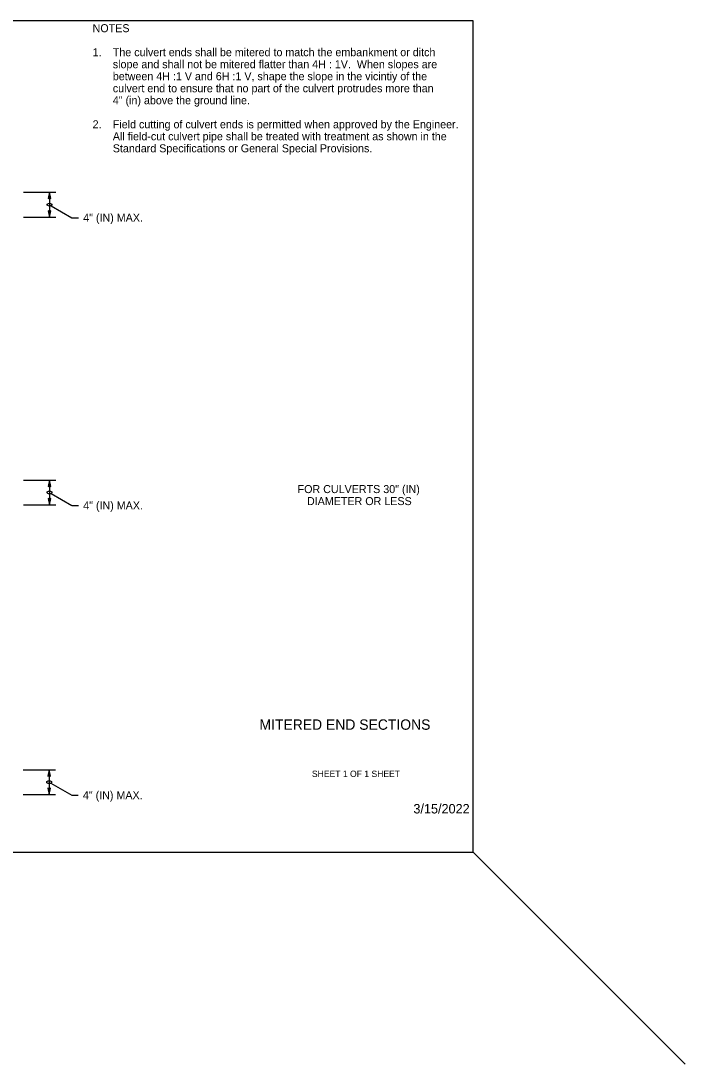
# Model space of a CAD drawing. Extents: x 99862 to 103680, y 99470 to 102076.
# Drawn here: x 102021 to 103680, y 99470 to 102076 of the extents above; entities that cross this region are included whole.
import ezdxf

# ---------------------------------------------------------------- set-up
doc = ezdxf.new("R2010")
doc.units = 0
for name, color, linetype in [('Default', 7, 'Continuous'), ('Level 1', 7, 'Continuous'), ('Level 15', 7, 'Continuous'), ('Level 20', 7, 'Continuous'), ('Level 60', 7, 'Continuous'), ('Level 62', 7, 'Continuous')]:
    doc.layers.add(name, color=color, linetype=linetype)

msp = doc.modelspace()

# ---------------------------------------------------------------- linework, layer by layer
at = {"layer": 'Default'}
for points in [[(102092.6, 101647.3), (102089.5, 101631.6), (102092.6, 101632.3), (102095.6, 101631.6)], [(102092.6, 101585.5), (102095.6, 101601.2), (102092.6, 101600.5), (102089.5, 101601.2)], [(102092.6, 100928.5), (102089.5, 100912.7), (102092.6, 100913.5), (102095.6, 100912.7)], [(102092.6, 100866.7), (102095.6, 100882.4), (102092.6, 100881.7), (102089.5, 100882.4)], [(102091.8, 100204.8), (102088.7, 100189.1), (102091.8, 100189.8), (102094.9, 100189.1)], [(102091.8, 100143), (102094.9, 100158.8), (102091.8, 100158), (102088.7, 100158.8)]]:
    msp.add_lwpolyline(points, close=True, dxfattribs=at)
at = {"layer": 'Level 1'}
msp.add_line((103150, 100000), (103680.3, 99469.7), dxfattribs=at)
msp.add_lwpolyline([(99862, 99999.5), (103151, 99999.5), (103151, 102075.5), (99862, 102075.5)], close=True, dxfattribs=at)
at = {"layer": 'Level 15'}
for p, q in [((102027.5, 101647.3), (102108.6, 101647.3)), ((102092.6, 101647.3), (102092.6, 101585.5)), ((102096.8, 101613.9), (102148.8, 101583.9)), ((102027.5, 101585.5), (102108.6, 101585.5)), ((102148.8, 101583.9), (102164.8, 101583.9)), ((102027.5, 100928.5), (102108.6, 100928.5)), ((102092.6, 100928.5), (102092.6, 100866.7)), ((102096.8, 100895.1), (102148.8, 100865.1)), ((102027.5, 100866.7), (102108.6, 100866.7)), ((102148.9, 100865.1), (102164.9, 100865.1)), ((102026.8, 100204.8), (102107.8, 100204.8)), ((102091.8, 100204.8), (102091.8, 100143)), ((102096.1, 100171.5), (102148.1, 100141.4)), ((102026.8, 100143), (102107.8, 100143)), ((102148.1, 100141.4), (102164.1, 100141.4))]:
    msp.add_line(p, q, dxfattribs=at)
for centre in [(102092.6, 101616.4), (102092.6, 100897.6), (102091.8, 100173.9)]:
    msp.add_ellipse(centre, major_axis=(-6, 0), ratio=0.57735, dxfattribs=at)
at = {"layer": 'Level 60'}
msp.add_line((103151, 102075.5), (103151, 102075.5), dxfattribs=at)

# ---------------------------------------------------------------- texts
at = {"layer": 'Level 15'}
msp.add_text('3/15/2022', height=23.62, dxfattribs=at).set_placement((103001.6, 100095.8))
at = {"layer": 'Level 20'}
for s, p in [('NOTES', (102200.3, 102047.2)), ('1.', (102200.3, 101987.2)), ('The culvert ends shall be mitered to match the embankment or ditch', (102250.8, 101987.2)), ('slope and shall not be mitered flatter than 4H : 1V.  When slopes are', (102250.8, 101957.2)), ('between 4H :1 V and 6H :1 V, shape the slope in the vicintiy of the', (102250.8, 101927.2)), ('culvert end to ensure that no part of the culvert protrudes more than', (102250.8, 101897.2)), ('4" (in) above the ground line.', (102250.8, 101867.2)), ('2.', (102200.3, 101807.2)), ('Field cutting of culvert ends is permitted when approved by the Engineer.', (102250.8, 101807.2)), ('All field-cut culvert pipe shall be treated with treatment as shown in the', (102250.8, 101777.2)), ('Standard Specifications or General Special Provisions.', (102250.8, 101747.2)), ('4" (IN) MAX.', (102176.9, 101573.9)), ('4" (IN) MAX.', (102176.9, 100855.1)), ('4" (IN) MAX.', (102176.1, 100131.4))]:
    msp.add_text(s, height=20, dxfattribs=at).set_placement(p)
at = {"layer": 'Level 62'}
for s, height, p in [('FOR CULVERTS 30" (IN)', 20, (102712.4, 100896)), ('DIAMETER OR LESS', 20, (102735.8, 100866)), ('MITERED END SECTIONS', 26, (102617.2, 100304.8)), ('SHEET 1 OF 1 SHEET', 16, (102748.2, 100186.8))]:
    msp.add_text(s, height=height, dxfattribs=at).set_placement(p)

doc.saveas('drawing.dxf')
